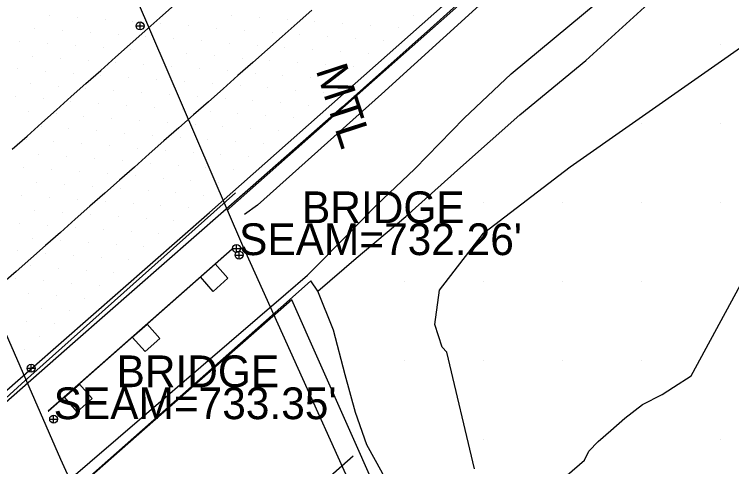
# Model space of a CAD drawing. Extents: x 1548934 to 1561348, y 809680 to 824075.
# Drawn here: x 1551840.5 to 1551931.4, y 810646.5 to 810703.8 of the extents above; entities that cross this region are included whole.
import ezdxf

# ---------------------------------------------------------------- set-up
doc = ezdxf.new("R2010")
doc.units = 0
for name, color, linetype in [('Default', 7, 'Continuous'), ('E_NCDOT_Vertical_Profile_Ground_Line', 7, 'Continuous'), ('Exist DTM QL2 LIDAR Elevation Point', 7, 'Continuous'), ('Exist DTM Scan Elevation Point', 7, 'Continuous'), ('Exist Guardrail', 7, 'Continuous'), ('Exist Guardrail Text', 7, 'Continuous'), ('Exist Structure Major Bridge Seam Top Elevation', 7, 'Continuous'), ('Exist Structure Major Deck Tunnel Box Culvert', 7, 'Continuous'), ('Exist Vegetation Woods Line', 7, 'Continuous'), ('P_RDY_Paved_Shoulder', 7, 'Continuous'), ('P_RDY_Terminator_Cell', 7, 'Continuous'), ('PH Exist DTM Breakline', 7, 'Continuous')]:
    doc.layers.add(name, color=color, linetype=linetype)

# ---------------------------------------------------------------- blocks, each defined once
blk = doc.blocks.new('SurveyPointCell')
at = {"layer": 'Default'}
for p, q in [((-0.5, 0), (0.5, 0)), ((0, -0.5), (0, 0.5))]:
    blk.add_line(p, q, dxfattribs=at)
blk.add_circle((0, 0), 0.5, dxfattribs=at)

msp = doc.modelspace()

# ---------------------------------------------------------------- linework, layer by layer
at = {"layer": 'E_NCDOT_Vertical_Profile_Ground_Line'}
msp.add_lwpolyline([(1551761.526, 810588.983), (1551784.506, 810608.402), (1551807.145, 810628.085), (1551829.828, 810647.718), (1551842.707, 810658.962), (1551865.26, 810678.743), (1551887.773, 810698.643), (1551911.033, 810719.298)], dxfattribs=at)
at = {"layer": 'Exist DTM QL2 LIDAR Elevation Point'}
for p, q in [((1551930.013, 810699.987), (1551930.013, 810699.987)), ((1551920.012, 810689.986), (1551920.012, 810689.986)), ((1551930.013, 810689.986), (1551930.013, 810689.986)), ((1551900.011, 810679.985), (1551900.011, 810679.985)), ((1551910.012, 810679.985), (1551910.012, 810679.985)), ((1551920.012, 810679.985), (1551920.012, 810679.985)), ((1551930.013, 810679.985), (1551930.013, 810679.985)), ((1551890.01, 810669.984), (1551890.01, 810669.984)), ((1551900.011, 810669.984), (1551900.011, 810669.984)), ((1551910.012, 810669.984), (1551910.012, 810669.984)), ((1551920.012, 810669.984), (1551920.012, 810669.984)), ((1551890.01, 810659.984), (1551890.01, 810659.984)), ((1551900.011, 810659.984), (1551900.011, 810659.984)), ((1551910.012, 810659.984), (1551910.012, 810659.984)), ((1551920.012, 810659.984), (1551920.012, 810659.984)), ((1551900.011, 810649.983), (1551900.011, 810649.983)), ((1551930.013, 810649.983), (1551930.013, 810649.983))]:
    msp.add_line(p, q, dxfattribs=at)
at = {"layer": 'Exist DTM Scan Elevation Point'}
for p, q in [((1551844.99, 810703.693), (1551844.99, 810703.693)), ((1551848.516, 810703.425), (1551848.516, 810703.425)), ((1551852.041, 810703.157), (1551852.041, 810703.157)), ((1551868.038, 810703.716), (1551868.038, 810703.716)), ((1551871.564, 810703.448), (1551871.564, 810703.448)), ((1551875.089, 810703.181), (1551875.089, 810703.181)), ((1551891.089, 810703.742), (1551891.089, 810703.742)), ((1551855.566, 810702.89), (1551855.566, 810702.89)), ((1551859.091, 810702.622), (1551859.091, 810702.622)), ((1551862.617, 810702.355), (1551862.617, 810702.355)), ((1551878.614, 810702.914), (1551878.614, 810702.914)), ((1551882.14, 810702.646), (1551882.14, 810702.646)), ((1551885.666, 810702.379), (1551885.666, 810702.379)), ((1551843.094, 810702.064), (1551843.094, 810702.064)), ((1551846.619, 810701.796), (1551846.619, 810701.796)), ((1551850.145, 810701.529), (1551850.145, 810701.529)), ((1551853.67, 810701.261), (1551853.67, 810701.261)), ((1551866.142, 810702.087), (1551866.142, 810702.087)), ((1551869.667, 810701.819), (1551869.667, 810701.819)), ((1551873.192, 810701.552), (1551873.192, 810701.552)), ((1551876.718, 810701.285), (1551876.718, 810701.285)), ((1551889.192, 810702.112), (1551889.192, 810702.112)), ((1551841.198, 810700.435), (1551841.198, 810700.435)), ((1551857.195, 810700.993), (1551857.195, 810700.993)), ((1551860.72, 810700.726), (1551860.72, 810700.726)), ((1551864.245, 810700.458), (1551864.245, 810700.458)), ((1551880.244, 810701.017), (1551880.244, 810701.017)), ((1551883.77, 810700.751), (1551883.77, 810700.751)), ((1551887.296, 810700.484), (1551887.296, 810700.484)), ((1551844.723, 810700.167), (1551844.723, 810700.167)), ((1551848.248, 810699.9), (1551848.248, 810699.9)), ((1551851.773, 810699.632), (1551851.773, 810699.632)), ((1551867.771, 810700.19), (1551867.771, 810700.19)), ((1551871.296, 810699.923), (1551871.296, 810699.923)), ((1551874.822, 810699.656), (1551874.822, 810699.656)), ((1551842.826, 810698.538), (1551842.826, 810698.538)), ((1551855.299, 810699.364), (1551855.299, 810699.364)), ((1551858.824, 810699.097), (1551858.824, 810699.097)), ((1551862.349, 810698.829), (1551862.349, 810698.829)), ((1551865.874, 810698.561), (1551865.874, 810698.561)), ((1551878.347, 810699.389), (1551878.347, 810699.389)), ((1551881.873, 810699.121), (1551881.873, 810699.121)), ((1551885.399, 810698.855), (1551885.399, 810698.855)), ((1551846.352, 810698.271), (1551846.352, 810698.271)), ((1551849.877, 810698.003), (1551849.877, 810698.003)), ((1551853.402, 810697.735), (1551853.402, 810697.735)), ((1551869.399, 810698.294), (1551869.399, 810698.294)), ((1551872.925, 810698.027), (1551872.925, 810698.027)), ((1551876.451, 810697.76), (1551876.451, 810697.76)), ((1551840.93, 810696.909), (1551840.93, 810696.909)), ((1551856.927, 810697.468), (1551856.927, 810697.468)), ((1551860.453, 810697.2), (1551860.453, 810697.2)), ((1551863.978, 810696.933), (1551863.978, 810696.933)), ((1551879.977, 810697.493), (1551879.977, 810697.493)), ((1551883.503, 810697.226), (1551883.503, 810697.226)), ((1551844.455, 810696.642), (1551844.455, 810696.642)), ((1551847.981, 810696.374), (1551847.981, 810696.374)), ((1551851.506, 810696.106), (1551851.506, 810696.106)), ((1551855.031, 810695.839), (1551855.031, 810695.839)), ((1551867.503, 810696.665), (1551867.503, 810696.665)), ((1551871.029, 810696.398), (1551871.029, 810696.398)), ((1551874.555, 810696.131), (1551874.555, 810696.131)), ((1551878.08, 810695.864), (1551878.08, 810695.864)), ((1551842.559, 810695.013), (1551842.559, 810695.013)), ((1551858.556, 810695.571), (1551858.556, 810695.571)), ((1551862.081, 810695.304), (1551862.081, 810695.304)), ((1551865.607, 810695.036), (1551865.607, 810695.036)), ((1551881.606, 810695.597), (1551881.606, 810695.597)), ((1551846.084, 810694.745), (1551846.084, 810694.745)), ((1551849.609, 810694.478), (1551849.609, 810694.478)), ((1551853.135, 810694.21), (1551853.135, 810694.21)), ((1551869.132, 810694.769), (1551869.132, 810694.769)), ((1551872.658, 810694.502), (1551872.658, 810694.502)), ((1551876.184, 810694.235), (1551876.184, 810694.235)), ((1551840.663, 810693.384), (1551840.663, 810693.384)), ((1551844.188, 810693.116), (1551844.188, 810693.116)), ((1551856.66, 810693.942), (1551856.66, 810693.942)), ((1551860.185, 810693.675), (1551860.185, 810693.675)), ((1551863.71, 810693.407), (1551863.71, 810693.407)), ((1551867.236, 810693.14), (1551867.236, 810693.14)), ((1551879.71, 810693.968), (1551879.71, 810693.968)), ((1551847.713, 810692.849), (1551847.713, 810692.849)), ((1551851.238, 810692.581), (1551851.238, 810692.581)), ((1551854.763, 810692.313), (1551854.763, 810692.313)), ((1551870.762, 810692.873), (1551870.762, 810692.873)), ((1551874.288, 810692.606), (1551874.288, 810692.606)), ((1551877.814, 810692.339), (1551877.814, 810692.339)), ((1551842.292, 810691.487), (1551842.292, 810691.487)), ((1551858.289, 810692.046), (1551858.289, 810692.046)), ((1551861.814, 810691.778), (1551861.814, 810691.778)), ((1551865.34, 810691.511), (1551865.34, 810691.511)), ((1551845.817, 810691.22), (1551845.817, 810691.22)), ((1551849.342, 810690.952), (1551849.342, 810690.952)), ((1551852.867, 810690.684), (1551852.867, 810690.684)), ((1551856.392, 810690.417), (1551856.392, 810690.417)), ((1551868.865, 810691.244), (1551868.865, 810691.244)), ((1551872.391, 810690.977), (1551872.391, 810690.977)), ((1551875.917, 810690.71), (1551875.917, 810690.71)), ((1551843.92, 810689.591), (1551843.92, 810689.591)), ((1551859.918, 810690.149), (1551859.918, 810690.149)), ((1551863.443, 810689.882), (1551863.443, 810689.882)), ((1551866.969, 810689.615), (1551866.969, 810689.615)), ((1551847.445, 810689.323), (1551847.445, 810689.323)), ((1551850.971, 810689.056), (1551850.971, 810689.056)), ((1551854.496, 810688.788), (1551854.496, 810688.788)), ((1551870.495, 810689.348), (1551870.495, 810689.348)), ((1551874.021, 810689.081), (1551874.021, 810689.081)), ((1551842.024, 810687.962), (1551842.024, 810687.962)), ((1551845.549, 810687.694), (1551845.549, 810687.694)), ((1551858.021, 810688.52), (1551858.021, 810688.52)), ((1551861.547, 810688.253), (1551861.547, 810688.253)), ((1551865.073, 810687.986), (1551865.073, 810687.986)), ((1551868.599, 810687.719), (1551868.599, 810687.719)), ((1551849.074, 810687.427), (1551849.074, 810687.427)), ((1551852.599, 810687.159), (1551852.599, 810687.159)), ((1551856.125, 810686.891), (1551856.125, 810686.891)), ((1551872.125, 810687.452), (1551872.125, 810687.452)), ((1551843.653, 810686.065), (1551843.653, 810686.065)), ((1551859.65, 810686.624), (1551859.65, 810686.624)), ((1551863.176, 810686.357), (1551863.176, 810686.357)), ((1551866.702, 810686.09), (1551866.702, 810686.09)), ((1551870.228, 810685.823), (1551870.228, 810685.823)), ((1551847.178, 810685.798), (1551847.178, 810685.798)), ((1551850.703, 810685.53), (1551850.703, 810685.53)), ((1551854.228, 810685.262), (1551854.228, 810685.262)), ((1551857.754, 810684.995), (1551857.754, 810684.995)), ((1551841.756, 810684.436), (1551841.756, 810684.436)), ((1551845.282, 810684.169), (1551845.282, 810684.169)), ((1551861.28, 810684.728), (1551861.28, 810684.728)), ((1551864.806, 810684.461), (1551864.806, 810684.461)), ((1551868.332, 810684.194), (1551868.332, 810684.194)), ((1551848.807, 810683.901), (1551848.807, 810683.901)), ((1551852.332, 810683.633), (1551852.332, 810683.633)), ((1551855.858, 810683.366), (1551855.858, 810683.366)), ((1551859.383, 810683.099), (1551859.383, 810683.099)), ((1551843.385, 810682.54), (1551843.385, 810682.54)), ((1551846.91, 810682.272), (1551846.91, 810682.272)), ((1551862.909, 810682.832), (1551862.909, 810682.832)), ((1551866.435, 810682.565), (1551866.435, 810682.565)), ((1551850.436, 810682.005), (1551850.436, 810682.005)), ((1551853.961, 810681.737), (1551853.961, 810681.737)), ((1551857.487, 810681.47), (1551857.487, 810681.47)), ((1551841.489, 810680.911), (1551841.489, 810680.911)), ((1551845.014, 810680.643), (1551845.014, 810680.643)), ((1551848.539, 810680.376), (1551848.539, 810680.376)), ((1551861.013, 810681.203), (1551861.013, 810681.203)), ((1551864.539, 810680.936), (1551864.539, 810680.936)), ((1551852.065, 810680.108), (1551852.065, 810680.108)), ((1551855.591, 810679.841), (1551855.591, 810679.841)), ((1551859.117, 810679.574), (1551859.117, 810679.574)), ((1551843.118, 810679.014), (1551843.118, 810679.014)), ((1551846.643, 810678.747), (1551846.643, 810678.747)), ((1551862.643, 810679.307), (1551862.643, 810679.307)), ((1551850.168, 810678.479), (1551850.168, 810678.479)), ((1551853.694, 810678.212), (1551853.694, 810678.212)), ((1551857.22, 810677.945), (1551857.22, 810677.945)), ((1551860.746, 810677.678), (1551860.746, 810677.678)), ((1551841.221, 810677.385), (1551841.221, 810677.385)), ((1551844.746, 810677.118), (1551844.746, 810677.118)), ((1551848.272, 810676.851), (1551848.272, 810676.851)), ((1551851.798, 810676.583), (1551851.798, 810676.583)), ((1551855.324, 810676.316), (1551855.324, 810676.316)), ((1551858.85, 810676.049), (1551858.85, 810676.049)), ((1551842.85, 810675.489), (1551842.85, 810675.489)), ((1551846.376, 810675.222), (1551846.376, 810675.222)), ((1551849.901, 810674.954), (1551849.901, 810674.954)), ((1551853.427, 810674.687), (1551853.427, 810674.687)), ((1551856.953, 810674.42), (1551856.953, 810674.42)), ((1551840.954, 810673.86), (1551840.954, 810673.86)), ((1551844.479, 810673.593), (1551844.479, 810673.593)), ((1551848.005, 810673.325), (1551848.005, 810673.325)), ((1551851.531, 810673.058), (1551851.531, 810673.058)), ((1551855.057, 810672.792), (1551855.057, 810672.792)), ((1551842.583, 810671.964), (1551842.583, 810671.964)), ((1551846.109, 810671.697), (1551846.109, 810671.697)), ((1551849.635, 810671.43), (1551849.635, 810671.43)), ((1551853.161, 810671.163), (1551853.161, 810671.163)), ((1551840.687, 810670.335), (1551840.687, 810670.335)), ((1551844.212, 810670.068), (1551844.212, 810670.068)), ((1551847.738, 810669.801), (1551847.738, 810669.801)), ((1551851.264, 810669.534), (1551851.264, 810669.534)), ((1551842.316, 810668.439), (1551842.316, 810668.439)), ((1551845.842, 810668.172), (1551845.842, 810668.172)), ((1551849.368, 810667.905), (1551849.368, 810667.905)), ((1551843.946, 810666.543), (1551843.946, 810666.543)), ((1551847.471, 810666.276), (1551847.471, 810666.276)), ((1551842.049, 810664.914), (1551842.049, 810664.914)), ((1551845.575, 810664.647), (1551845.575, 810664.647)), ((1551843.679, 810663.018), (1551843.679, 810663.018)), ((1551841.782, 810661.389), (1551841.782, 810661.389))]:
    msp.add_line(p, q, dxfattribs=at)
at = {"layer": 'Exist Guardrail'}
for points in [[(1551904.412, 810712.079), (1551893.283, 810702.02), (1551882.055, 810692.075), (1551870.8, 810682.158), (1551859.512, 810672.281), (1551848.232, 810662.394), (1551836.949, 810652.511), (1551825.603, 810642.663)], [(1551904.559, 810711.811), (1551867.806, 810679.261), (1551867.548, 810679.035)]]:
    msp.add_lwpolyline(points, dxfattribs=at)
at = {"layer": 'Exist Structure Major Deck Tunnel Box Culvert'}
for points in [[(1551890.16, 810628.772), (1551869.489, 810674.52), (1551854.065, 810710.393), (1551839.842, 810744.541), (1551817.227, 810801.667), (1551801.118, 810844.761), (1551789.242, 810877.577)], [(1551763.353, 810854.68), (1551776.069, 810819.842), (1551783.152, 810800.687), (1551795.344, 810769.157), (1551805.495, 810743.337), (1551817.592, 810713.867), (1551830.145, 810684.596), (1551846.388, 810647.478), (1551862.114, 810612.886), (1551864.95, 810606.898)]]:
    msp.add_lwpolyline(points, dxfattribs=at)
for points in [[(1551844.872, 810653.588), (1551868.141, 810674.101), (1551868.141, 810674.101), (1551861.378, 810668.14), (1551861.378, 810668.14), (1551854.632, 810662.191), (1551854.632, 810662.191), (1551847.879, 810656.239), (1551847.879, 810656.239), (1551844.839, 810653.558), (1551844.839, 810653.558)], [(1551867.606, 810670.414), (1551865.725, 810668.749), (1551864.109, 810670.574), (1551865.99, 810672.239)], [(1551858.98, 810662.777), (1551857.099, 810661.112), (1551855.483, 810662.937), (1551857.364, 810664.603)], [(1551850.395, 810655.176), (1551848.514, 810653.511), (1551846.898, 810655.337), (1551848.779, 810657.002)]]:
    msp.add_lwpolyline(points, close=True, dxfattribs=at)
at = {"layer": 'Exist Vegetation Woods Line'}
msp.add_lwpolyline([(1551898.835, 810646.281), (1551895.343, 810661.057), (1551894.744, 810661.687), (1551893.819, 810664.542), (1551894.425, 810668.881), (1551899.995, 810676.115), (1551910.956, 810684.524), (1551943.415, 810707.255), (1551974.868, 810738.059), (1551997.823, 810758.805), (1552013.848, 810771.925), (1552029.065, 810783.632), (1552036.38, 810788.865), (1552045.031, 810794.294)], dxfattribs=at)
at = {"layer": 'P_RDY_Paved_Shoulder'}
for points in [[(1551875.682, 810667.671), (1551860.193, 810654.089), (1551848.932, 810644.178), (1551847.914, 810643.08), (1551844.156, 810638.55), (1551842.634, 810637.243)], [(1551847.945, 810638.332), (1551861.118, 810609.555), (1551880.149, 810626.851), (1551890.043, 810635.354), (1551875.682, 810667.671)]]:
    msp.add_lwpolyline(points, dxfattribs=at)
at = {"layer": 'P_RDY_Terminator_Cell'}
for points in [[(1551840.273, 810686.762), (1551842.144, 810688.42), (1551844.011, 810690.082), (1551845.879, 810691.744), (1551847.746, 810693.406), (1551849.614, 810695.068), (1551851.481, 810696.73), (1551853.349, 810698.392), (1551855.216, 810700.054), (1551857.084, 810701.716), (1551858.951, 810703.379), (1551860.818, 810705.041)], [(1551878.22, 810704.359), (1551876.353, 810702.696), (1551874.486, 810701.033), (1551872.616, 810699.374), (1551870.741, 810697.72), (1551868.867, 810696.066), (1551866.992, 810694.412), (1551865.118, 810692.758), (1551863.243, 810691.104), (1551861.368, 810689.45), (1551859.494, 810687.796), (1551857.619, 810686.142), (1551855.745, 810684.488), (1551853.87, 810682.834), (1551851.995, 810681.18), (1551850.121, 810679.526), (1551848.246, 810677.871), (1551846.371, 810676.217), (1551844.497, 810674.563), (1551842.622, 810672.909), (1551840.748, 810671.255), (1551838.873, 810669.601)], [(1551855.593, 810623.467), (1551871.357, 810637.229), (1551883.481, 810647.937)]]:
    msp.add_lwpolyline(points, dxfattribs=at)
at = {"layer": 'PH Exist DTM Breakline'}
for points in [[(1552034.682, 810827.336), (1552009.032, 810803.562), (1551989.606, 810785.597), (1551967.508, 810765.691), (1551937.585, 810738.553), (1551910.971, 810715.467), (1551887.069, 810693.706), (1551871.355, 810679.667), (1551869.7, 810678.494)], [(1551846.494, 810644.052), (1551874.918, 810668.424), (1551877.701, 810670.808), (1551882.752, 810675.884), (1551886.428, 810679.663), (1551891.289, 810684.268), (1551897.528, 810690.665), (1551903.503, 810696.296), (1551914.364, 810705.329), (1551920.689, 810710.86), (1551930.296, 810719.132), (1551939.693, 810727.24), (1551951.117, 810736.833), (1551959.915, 810744.861), (1551966.776, 810750.897), (1551976.785, 810760.434), (1551991.407, 810773.635), (1552001.876, 810782.888), (1552013.774, 810794.041), (1552028.845, 810808.12), (1552037.768, 810816.551)], [(1551878.984, 810668.784), (1551883.861, 810672.937), (1551890.136, 810678.245), (1551897.077, 810684.45), (1551904.567, 810691.092), (1551912.952, 810697.967), (1551920.388, 810704.722), (1551928.87, 810712.297), (1551938.41, 810720.844), (1551945.379, 810727.377), (1551955.987, 810736.211), (1551966.503, 810745.64), (1551974.191, 810752.575), (1551991.138, 810768.586), (1552011.162, 810786.108), (1552020.288, 810794.024), (1552028.602, 810801.76), (1552037.687, 810810.1), (1552040.662, 810813.069)], [(1551910.584, 810645.462), (1551912.771, 810647.379), (1551913.317, 810648.53), (1551914.503, 810649.731), (1551916.095, 810651.136), (1551917.88, 810652.67), (1551920.124, 810654.428), (1551922.61, 810655.673), (1551924.069, 810656.613), (1551926.301, 810658.067), (1551933.076, 810670.591), (1551934.061, 810672.857), (1551936.43, 810675.436), (1551941.415, 810682.418), (1551959.678, 810697.606), (1551971.325, 810708.879), (1551979.735, 810715.647), (1551990.355, 810724.938), (1551996.688, 810731.324)], [(1551830.951, 810647.491), (1551841.446, 810657.057), (1551868.548, 810681.239)], [(1551892.244, 810632.878), (1551891.724, 810634.711), (1551890.983, 810636.913), (1551889.086, 810641.35), (1551887.164, 810645.732), (1551885.218, 810649.299), (1551883.756, 810653.398), (1551882.453, 810658.181), (1551880.972, 810663.842), (1551878.984, 810668.784), (1551878.115, 810670.089), (1551875.381, 810667.681), (1551847.255, 810642.799), (1551846.513, 810641.391)]]:
    msp.add_lwpolyline(points, dxfattribs=at)

# ---------------------------------------------------------------- block references
at = {"layer": 'Default'}
for p in [(1551856.468, 810702.361), (1551868.682, 810674.182), (1551869.01, 810673.337), (1551842.666, 810659.01), (1551845.513, 810652.563)]:
    msp.add_blockref('SurveyPointCell', p, dxfattribs=at)

# ---------------------------------------------------------------- texts
at = {"layer": 'Exist Guardrail Text'}
msp.add_text('MTL', height=4.02, rotation=288.09027, dxfattribs=at).set_placement((1551878.692, 810696.78))
at = {"layer": 'Exist Structure Major Bridge Seam Top Elevation'}
for s, p in [('BRIDGE', (1551876.982, 810677.384)), ("SEAM=732.26'", (1551869.01, 810673.337)), ('BRIDGE', (1551853.484, 810656.61)), ("SEAM=733.35'", (1551845.513, 810652.563))]:
    msp.add_text(s, height=4.02, dxfattribs=at).set_placement(p)

doc.saveas('drawing.dxf')
